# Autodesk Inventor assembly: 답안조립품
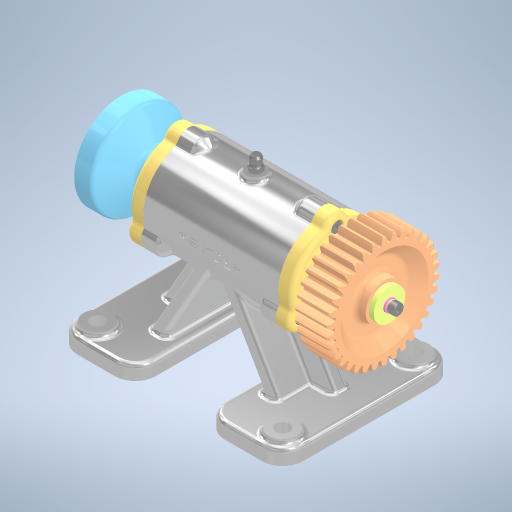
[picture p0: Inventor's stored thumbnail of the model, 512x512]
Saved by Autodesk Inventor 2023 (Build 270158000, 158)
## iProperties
Created: 2026-04
Part Number: 답안조립품
Document SubType Name: Assembly
Designer: 4강의실
Author: 4강의실
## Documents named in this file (16)
- C:\Users\kimgi\Desktop\760403V1005\답안조립품.iam
- C:\Users\kimgi\Desktop\760403V1005\본체.ipt
- C:\Users\kimgi\Desktop\760403V1005\실링.ipt
- C:\Users\kimgi\Desktop\760403V1005\플러그 M6x0,75.ipt
- C:\Users\kimgi\Desktop\760403V1005\그리스 니플 M6x0,75.ipt
- C:\Users\kimgi\Desktop\760403V1005\깊은 홈 볼 베어링 6004.ipt
- C:\Users\kimgi\Desktop\760403V1005\축.ipt
- C:\Users\kimgi\Desktop\760403V1005\커버.ipt
- C:\Users\kimgi\Desktop\760403V1005\오일 실 20 35 8.ipt
- C:\Users\kimgi\Desktop\760403V1005\평행 키 4x4x14.ipt
- C:\Users\kimgi\Desktop\760403V1005\플랜지.ipt
- C:\Users\kimgi\Desktop\760403V1005\엔드 캡.ipt
- C:\Users\kimgi\Desktop\760403V1005\평 와셔 M4.ipt
- C:\Users\kimgi\Desktop\760403V1005\스프링 와셔 M4.ipt
- C:\Users\kimgi\Desktop\760403V1005\6각 구멍붙이 볼트 M4x12.ipt
- C:\Users\kimgi\Desktop\760403V1005\스퍼 기어.ipt
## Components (11 placed, 4 different names)
1. 플러그 M6x0,75:1
2. 그리스 니플 M6x0,75:1
3. 플랜지:1
4. 6각 구멍붙이 볼트 M4x12:1
5. 6각 구멍붙이 볼트 M4x12:2
6. 6각 구멍붙이 볼트 M4x12:3
7. 6각 구멍붙이 볼트 M4x12:4
8. 6각 구멍붙이 볼트 M4x12:5
9. 6각 구멍붙이 볼트 M4x12:6
10. 6각 구멍붙이 볼트 M4x12:7
11. 6각 구멍붙이 볼트 M4x12:8
